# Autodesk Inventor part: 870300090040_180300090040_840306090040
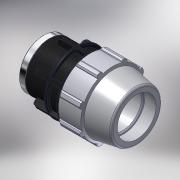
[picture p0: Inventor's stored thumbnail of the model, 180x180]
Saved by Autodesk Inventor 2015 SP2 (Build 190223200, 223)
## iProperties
Created: 2017-02
Part Number: 870300090040_180300090040_840306090040
Material: PVC-Piping
Description: PLASSON FEMALE ADAPTOR 90-4"
Document SubType Name: Modeling
Designer: KIM
Mass: 92.6774 g
Surface Area: 199.44 cm^2
Volume: 66.1981 cm^3
Density: 1.4 g/cm^3
Appearance: PTFE
Author: KIM
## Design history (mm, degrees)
derived "87030.ipt"
feature "Solid1::87030.ipt"
tag "TaggingFeature1"
body "Solid1"
other parameters: "d4" = 34.57143, "d5" = 60.5, "d7" = 152, "d9" = 34.57143, "d11" = 6.91429, "d12" = 121.6, "d13" = 120 deg, "d14" = 117, "d15" = 8 deg, "d16" = 136.8, "d18" = 4.5, "d19" = 35 deg, "d20" = 17.5 deg, "d21" = 141.36, "d23" = 0, "d25" = 360 deg, "d27" = 3.04, "d34" = 7.6, "d35" = 72.6, "d36" = 0, "d42" = 60.5, "d43" = 4.56, "d46" = 2.7, "d49" = 182, "d51" = 242, "d53" = 1.8, "d55" = 360 deg, "d62" = 72, "d63" = 110.072, "d64" = 80.66667, "d65" = 7.6, "d69" = 121.6, "d70" = 3.8, "d71" = 12.6, "d72" = 0.5, "d73" = 1, "E_" = 152, "H_" = 242, "l_" = 182, "Rp_Rc_" = 110.072
